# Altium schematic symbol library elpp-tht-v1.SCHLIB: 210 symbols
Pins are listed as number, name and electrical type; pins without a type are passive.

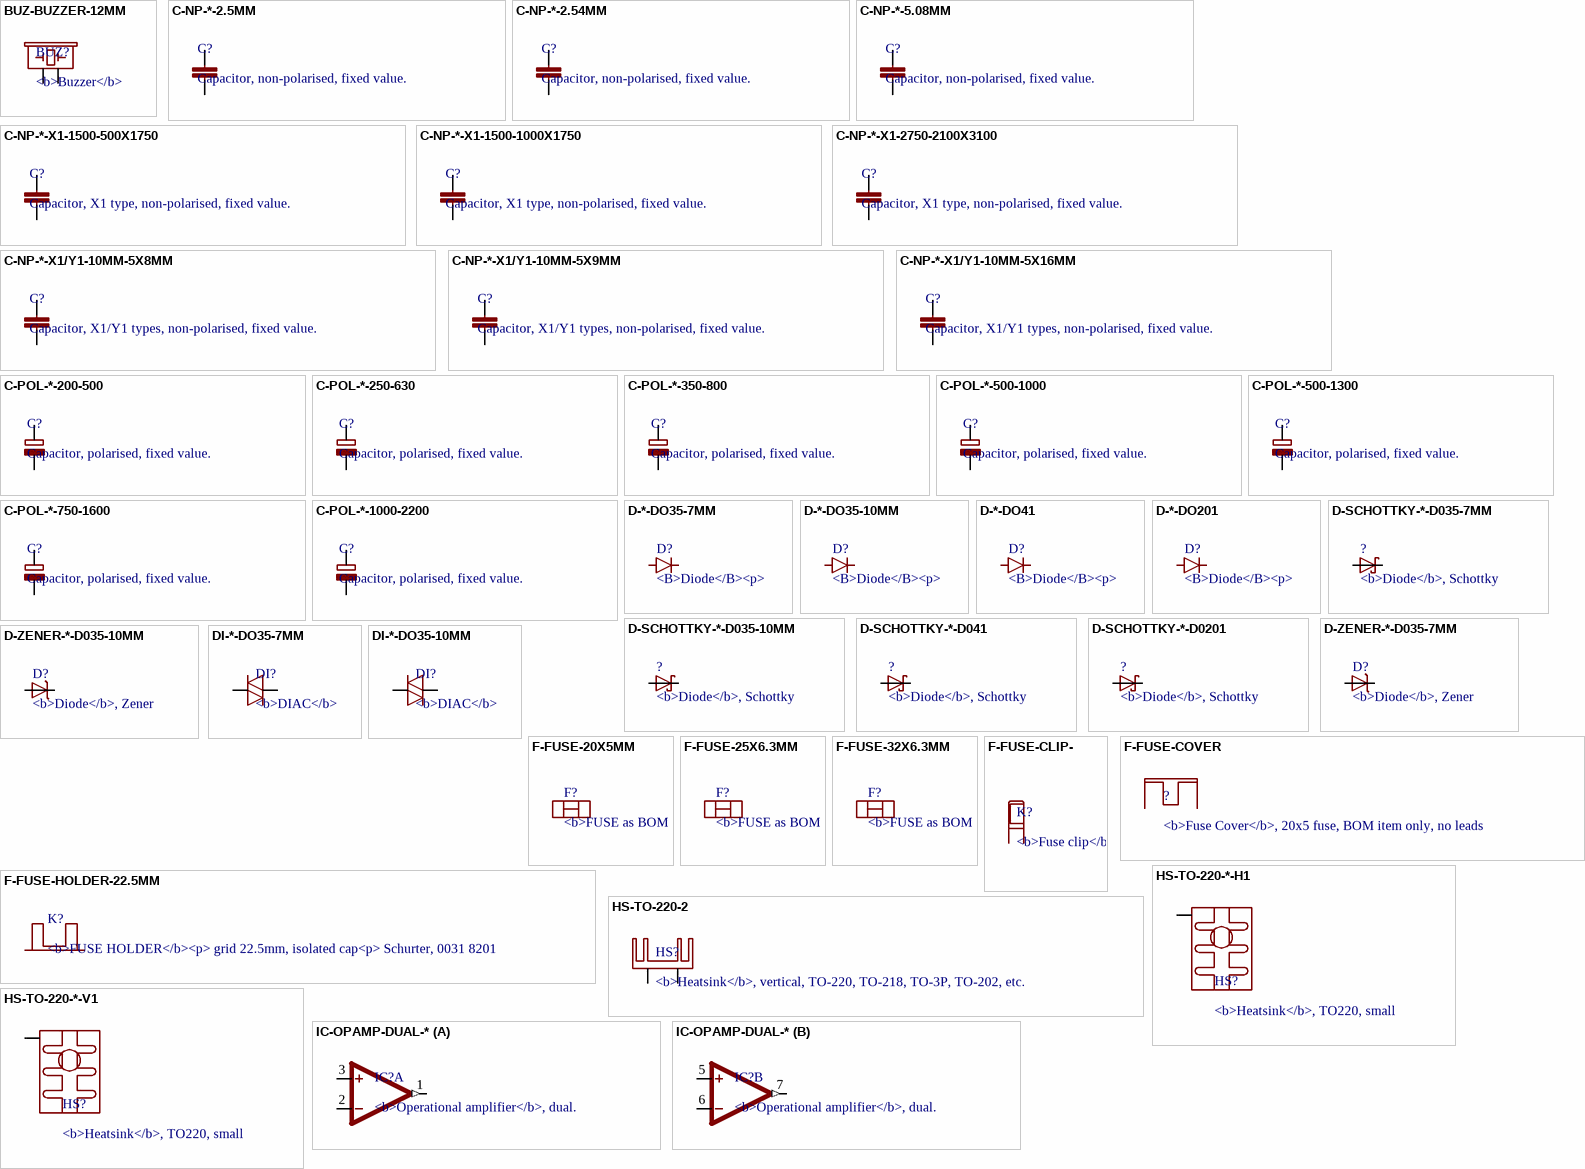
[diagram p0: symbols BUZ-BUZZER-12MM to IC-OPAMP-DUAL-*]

## BUZ-BUZZER-12MM
designator BUZ?, comment <b>Buzzer</b>
RS: 6173081
footprint ELPP-BUZZER-12MM
pins: + 1, - 2

## C-NP-*-2.5MM
designator C?, comment Capacitor, non-polarised, fixed value.
RS: 5373549; RS: 5373634; RS: 6994982; RS: 2114921
footprint ELPP-CNP-250
pins: 1, 2

## C-NP-*-2.54MM
designator C?, comment Capacitor, non-polarised, fixed value.
RS: 7368827; RS: 7368820; RS: 6530131; RS: 7368823; RS: 7368836
footprint ELPP-CNP-254
pins: 1, 2

## C-NP-*-5.08MM
designator C?, comment Capacitor, non-polarised, fixed value.
RS: 5373707; RS: 7215265; RS: 5373915; RS: 6530147
footprint ELPP-CNP-508
pins: 1, 2

## C-NP-*-X1-1500-500X1750
designator C?, comment Capacitor, X1 type, non-polarised, fixed value.
RS: 6842153
footprint ELPP-CNP-1500-500X1750
pins: 1, 2

## C-NP-*-X1-1500-1000X1750
designator C?, comment Capacitor, X1 type, non-polarised, fixed value.
RS: 6842169
footprint ELPP-CNP-1500-1000X1750
pins: 1, 2

## C-NP-*-X1-2750-2100X3100
designator C?, comment Capacitor, X1 type, non-polarised, fixed value.
RS: 6842175
footprint ELPP-CNP-2750-2100X3100
pins: 1, 2

## C-NP-*-X1/Y1-10MM-5X8MM
designator C?, comment Capacitor, X1/Y1 types, non-polarised, fixed value.
RS: 7368934
footprint ELPP-CNP-1000-500X800
pins: 1, 2

## C-NP-*-X1/Y1-10MM-5X9MM
designator C?, comment Capacitor, X1/Y1 types, non-polarised, fixed value.
RS: 7368946
footprint ELPP-CNP-1000-500X900
pins: 1, 2

## C-NP-*-X1/Y1-10MM-5X16MM
designator C?, comment Capacitor, X1/Y1 types, non-polarised, fixed value.
RS: 7368952
footprint ELPP-CNP-1000-500X1600
pins: 1, 2

## C-POL-*-200-500
designator C?, comment Capacitor, polarised, fixed value.
RS: 2286830; RS: 2286874; RS: 2286846; RS: 2286852; RS: 2286880; RS: 2286868
footprint ELPP-CP-200-500
pins: +, -

## C-POL-*-250-630
designator C?, comment Capacitor, polarised, fixed value.
RS: 2286896
footprint ELPP-CP-250-630
pins: +, -

## C-POL-*-350-800
designator C?, comment Capacitor, polarised, fixed value.
RS: 2286903
footprint ELPP-CP-350-800
pins: +, -

## C-POL-*-500-1000
designator C?, comment Capacitor, polarised, fixed value.
RS: 2286919
footprint ELPP-CP-500-1000
pins: +, -

## C-POL-*-500-1300
designator C?, comment Capacitor, polarised, fixed value.
RS: 2286925
footprint ELPP-CP-500-1300
pins: +, -

## C-POL-*-750-1600
designator C?, comment Capacitor, polarised, fixed value.
RS: 2287013; RS: 3654335
footprint ELPP-CP-750-1600
pins: +, -

## C-POL-*-1000-2200
designator C?, comment Capacitor, polarised, fixed value.
RS: 7111526
footprint ELPP-CP-1000-2200
pins: +, -

## D-*-DO35-7MM
designator D?, comment <B>Diode</B><p>
RS: 5443480
footprint ELPP-DO-35-7MM
pins: A, C

## D-*-DO35-10MM
designator D?, comment <B>Diode</B><p>
RS: 5443480
footprint ELPP-DO-35-10MM
pins: A, C

## D-*-DO41
designator D?, comment <B>Diode</B><p>
RS: 6715468
footprint ELPP-DO-41
pins: A, C

## D-*-DO201
designator D?, comment <B>Diode</B><p>
RS: 7003879
footprint ELPP-DO-201AD
pins: A, C

## D-SCHOTTKY-*-D035-7MM
designator ?, comment <b>Diode</b>, Schottky
RS: 7003857
footprint ELPP-DO-35-7MM
pins: A, C

## D-SCHOTTKY-*-D035-10MM
designator ?, comment <b>Diode</b>, Schottky
RS: 7003857
footprint ELPP-DO-35-10MM
pins: A, C

## D-SCHOTTKY-*-D041
designator ?, comment <b>Diode</b>, Schottky
RS: 7146807
footprint ELPP-DO-41
pins: A, C

## D-SCHOTTKY-*-D0201
designator ?, comment <b>Diode</b>, Schottky
RS: 7010215
footprint ELPP-DO-201AD
pins: A, C

## D-ZENER-*-D035-7MM
designator D?, comment <b>Diode</b>, Zener
RS: 6997783; RS: 6997792; RS: 7087883; RS: 6997799; RS: 6997802
footprint ELPP-DO-35-7MM
pins: A, C

## D-ZENER-*-D035-10MM
designator D?, comment <b>Diode</b>, Zener
RS: 6997783; RS: 6997792; RS: 7087883; RS: 6997799; RS: 6997802
footprint ELPP-DO-35-10MM
pins: A, C

## DI-*-DO35-7MM
designator DI?, comment <b>DIAC</b>
RS: 108132
footprint ELPP-DO-35-7MM
pins: A 1, C 2

## DI-*-DO35-10MM
designator DI?, comment <b>DIAC</b>
RS: 108132
footprint ELPP-DO-35-10MM
pins: A 1, C 2

## F-FUSE-20X5MM
designator F?, comment <b>FUSE as BOM item</b><p>No leads, add <u>one</u> fuse holder or <u>two</u> fuse clips for fuse leads</p>
footprint ELPP-FUSE-2000X500

## F-FUSE-25X6.3MM
designator F?, comment <b>FUSE as BOM item</b><p>No leads, add <u>one</u> fuse holder or <u>two</u> fuse clips for fuse leads</p>
footprint ELPP-FUSE-2500X630

## F-FUSE-32X6.3MM
designator F?, comment <b>FUSE as BOM item</b><p>No leads, add <u>one</u> fuse holder or <u>two</u> fuse clips for fuse leads</p>
footprint ELPP-FUSE-3200X630

## F-FUSE-CLIP-
designator K?, comment <b>Fuse clip</b> for 6.3mm diameter fuses.<br>You need two of these for one fuse.
RS: 7032798
footprint ELPP-FUSE-CLIP
pins: 1A 1, 1B 2

## F-FUSE-COVER
designator ?, comment <b>Fuse Cover</b>, 20x5 fuse, BOM item only, no leads
RS: 1769069

## F-FUSE-HOLDER-22.5MM
designator K?, comment <b>FUSE HOLDER</b><p> grid 22.5mm, isolated cap<p> Schurter, 0031 8201
RS: 1769047
footprint ELPP-FUSE-HOLDER-2000X500
pins: 1, 2

## HS-TO-220-2
designator HS?, comment <b>Heatsink</b>, vertical, TO-220, TO-218, TO-3P, TO-202, etc.
RS: 403190
footprint ELPP-HS-TO-220-V2
pins: 1 (oe), 2 (oe)

## HS-TO-220-*-H1
designator HS?, comment <b>Heatsink</b>, TO220, small
RS: 268082
footprint ELPP-HS-TO-220-H1
pins: 1

## HS-TO-220-*-V1
designator HS?, comment <b>Heatsink</b>, TO220, small
RS: 7124248
footprint ELPP-HS-TO-220-V1
pins: 1

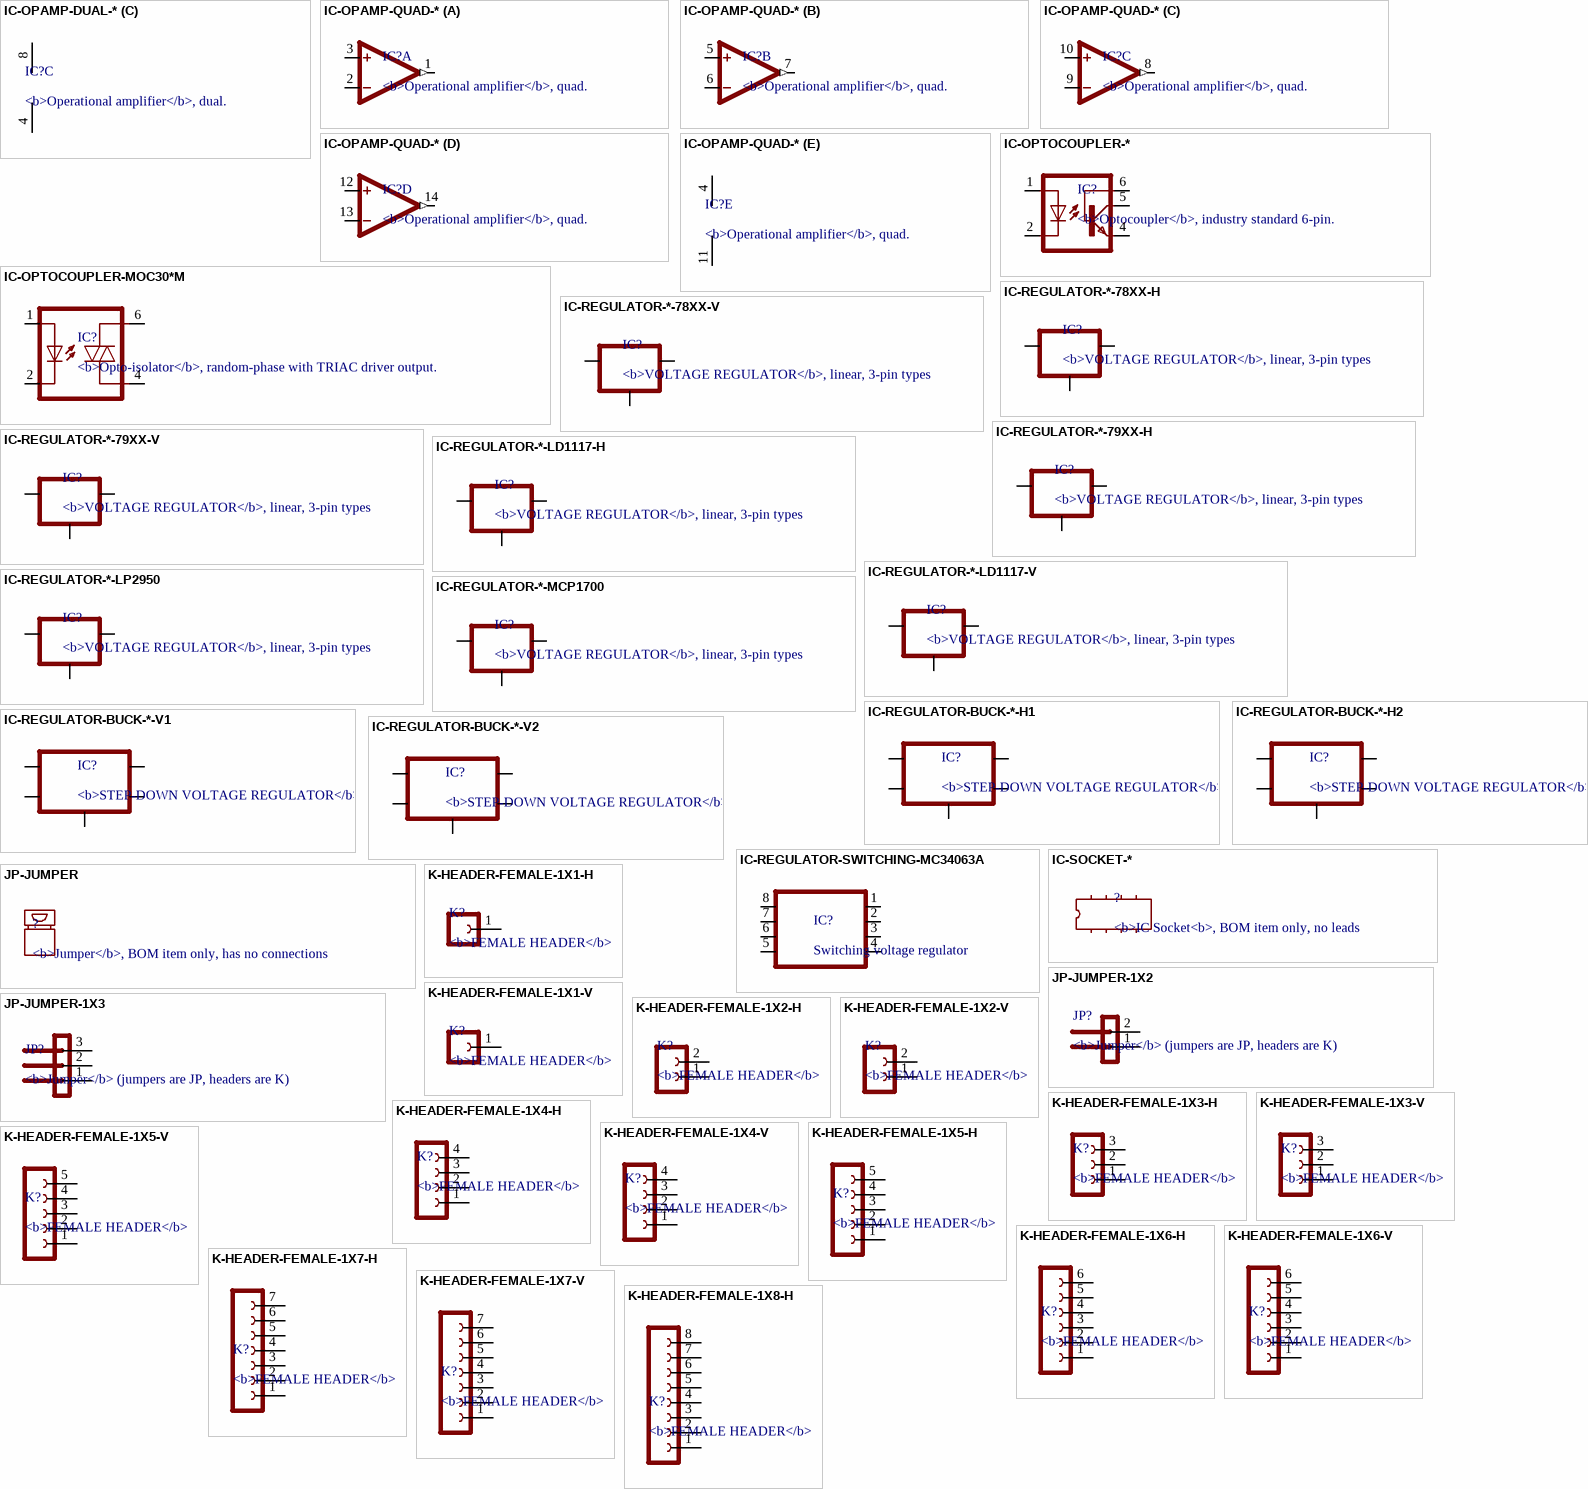
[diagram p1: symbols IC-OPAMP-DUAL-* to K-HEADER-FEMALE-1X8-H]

## IC-OPAMP-DUAL-*
designator IC?, comment <b>Operational amplifier</b>, dual.
RS: 7613546; RS: 4363046; RS: 304239
footprint ELPP-DIP-8
part A pins: 1 OUT (out), 2 -IN, 3 +IN
part B pins: 5 +IN, 6 -IN, 7 OUT (out)
part C pins: 4 V-, 8 V+

## IC-OPAMP-QUAD-*
designator IC?, comment <b>Operational amplifier</b>, quad.
RS: 6610530; RS: 403181; RS: 302621
footprint ELPP-DIP-14
part A pins: 1 OUT (out), 2 -IN, 3 +IN
part B pins: 5 +IN, 6 -IN, 7 OUT (out)
part C pins: 8 OUT (out), 9 -IN, 10 +IN
part D pins: 12 +IN, 13 -IN, 14 OUT (out)
part E pins: 4 V+, 11 V-

## IC-OPTOCOUPLER-*
designator IC?, comment <b>Optocoupler</b>, industry standard 6-pin.
RS: 6998155
footprint ELPP-DIP-6
pins: 1 A, 2 C, 4 EMI, 5 COL, 6 BAS

## IC-OPTOCOUPLER-MOC30*M
designator IC?, comment <b>Opto-isolator</b>, random-phase with TRIAC driver output.
RS: 6711422
footprint ELPP-DIP-6
pins: 1 A, 2 C, 4 A1, 6 A2

## IC-REGULATOR-*-78XX-H
designator IC?, comment <b>VOLTAGE REGULATOR</b>, linear, 3-pin types
RS: 5164834; RS: 5164840; RS: 5164799; RS: 5164812
footprint ELPP-TO-220-H
pins: 1 VI, 2 COM, 3 VO

## IC-REGULATOR-*-78XX-V
designator IC?, comment <b>VOLTAGE REGULATOR</b>, linear, 3-pin types
RS: 5164834; RS: 5164840; RS: 5164799; RS: 5164812
footprint ELPP-TO-220-V
pins: 1 VI, 2 COM, 3 VO

## IC-REGULATOR-*-79XX-H
designator IC?, comment <b>VOLTAGE REGULATOR</b>, linear, 3-pin types
RS: 5166228
footprint ELPP-TO-220-H
pins: 1 VI, 2 COM, 3 VO

## IC-REGULATOR-*-79XX-V
designator IC?, comment <b>VOLTAGE REGULATOR</b>, linear, 3-pin types
RS: 5166228
footprint ELPP-TO-220-V
pins: 1 VI, 2 COM, 3 VO

## IC-REGULATOR-*-LD1117-H
designator IC?, comment <b>VOLTAGE REGULATOR</b>, linear, 3-pin types
RS: 6869767
footprint ELPP-TO-220-H
pins: 1 COM, 2 VO, 3 VI

## IC-REGULATOR-*-LD1117-V
designator IC?, comment <b>VOLTAGE REGULATOR</b>, linear, 3-pin types
RS: 6869767
footprint ELPP-TO-220-V
pins: 1 COM, 2 VO, 3 VI

## IC-REGULATOR-*-LP2950
designator IC?, comment <b>VOLTAGE REGULATOR</b>, linear, 3-pin types
RS: 5344901
footprint ELPP-TO-92
pins: 1 VO, 2 COM, 3 VI

## IC-REGULATOR-*-MCP1700
designator IC?, comment <b>VOLTAGE REGULATOR</b>, linear, 3-pin types
RS: 403888
footprint ELPP-TO-92
pins: 1 COM, 2 VI, 3 VO

## IC-REGULATOR-BUCK-*-H1
designator IC?, comment <b>STEP-DOWN VOLTAGE REGULATOR</b>
RS: 5338108
footprint ELPP-TO-220-5-H
pins: 1 VI, 2 VO, 3 COM, 4 FB, 5 EN

## IC-REGULATOR-BUCK-*-H2
designator IC?, comment <b>STEP-DOWN VOLTAGE REGULATOR</b>
RS: 5338108
footprint ELPP-TO-220-5-H-STAGGERED
pins: 1 VI, 2 VO, 3 COM, 4 FB, 5 EN

## IC-REGULATOR-BUCK-*-V1
designator IC?, comment <b>STEP-DOWN VOLTAGE REGULATOR</b>
RS: 5338108
footprint ELPP-TO-220-5-V
pins: 1 VI, 2 VO, 3 COM, 4 FB, 5 EN

## IC-REGULATOR-BUCK-*-V2
designator IC?, comment <b>STEP-DOWN VOLTAGE REGULATOR</b>
RS: 5338108
footprint ELPP-TO-220-5-V-STAGGERED
pins: 1 VI, 2 VO, 3 COM, 4 FB, 5 EN

## IC-REGULATOR-SWITCHING-MC34063A
designator IC?, comment Switching voltage regulator
RS: 6618430
footprint ELPP-DIP-8
pins: 1, 2, 3, 4, 5, 6, 7, 8

## IC-SOCKET-*
designator ?, comment <b>IC Socket<b>, BOM item only, no leads
RS: 7020676; RS: 7020688; RS: 7022723; RS: 7022726; RS: 7022745; RS: 7022798; RS: 7020657; RS: 7020654

## JP-JUMPER
designator ?, comment <b>Jumper</b>, BOM item only, has no connections
RS: 2509565244

## JP-JUMPER-1X2
designator JP?, comment <b>Jumper</b> (jumpers are JP, headers are K)
RS: 6812058
footprint ELPP-SIL-M-2-WAY
pins: 1, 2

## JP-JUMPER-1X3
designator JP?, comment <b>Jumper</b> (jumpers are JP, headers are K)
RS: 6812058
footprint ELPP-SIL-M-3-WAY
pins: 1, 2, 3

## K-HEADER-FEMALE-1X1-H
designator K?, comment <b>FEMALE HEADER</b>
RS: unknown
footprint ELPP-SIL-F-1-WAY-90DEG
pins: 1

## K-HEADER-FEMALE-1X1-V
designator K?, comment <b>FEMALE HEADER</b>
RS: unknown
footprint ELPP-SIL-F-1-WAY
pins: 1

## K-HEADER-FEMALE-1X2-H
designator K?, comment <b>FEMALE HEADER</b>
RS: unknown
footprint ELPP-SIL-F-2-WAY-90DEG
pins: 1, 2

## K-HEADER-FEMALE-1X2-V
designator K?, comment <b>FEMALE HEADER</b>
RS: unknown
footprint ELPP-SIL-F-2-WAY
pins: 1, 2

## K-HEADER-FEMALE-1X3-H
designator K?, comment <b>FEMALE HEADER</b>
RS: unknown
footprint ELPP-SIL-F-3-WAY-90DEG
pins: 1, 2, 3

## K-HEADER-FEMALE-1X3-V
designator K?, comment <b>FEMALE HEADER</b>
RS: unknown
footprint ELPP-SIL-F-3-WAY
pins: 1, 2, 3

## K-HEADER-FEMALE-1X4-H
designator K?, comment <b>FEMALE HEADER</b>
RS: unknown
footprint ELPP-SIL-F-4-WAY-90DEG
pins: 1, 2, 3, 4

## K-HEADER-FEMALE-1X4-V
designator K?, comment <b>FEMALE HEADER</b>
RS: unknown
footprint ELPP-SIL-F-4-WAY
pins: 1, 2, 3, 4

## K-HEADER-FEMALE-1X5-H
designator K?, comment <b>FEMALE HEADER</b>
RS: unknown
footprint ELPP-SIL-F-5-WAY-90DEG
pins: 1, 2, 3, 4, 5

## K-HEADER-FEMALE-1X5-V
designator K?, comment <b>FEMALE HEADER</b>
RS: unknown
footprint ELPP-SIL-F-5-WAY
pins: 1, 2, 3, 4, 5

## K-HEADER-FEMALE-1X6-H
designator K?, comment <b>FEMALE HEADER</b>
RS: unknown
footprint ELPP-SIL-F-6-WAY-90DEG
pins: 1, 2, 3, 4, 5, 6

## K-HEADER-FEMALE-1X6-V
designator K?, comment <b>FEMALE HEADER</b>
RS: unknown
footprint ELPP-SIL-F-6-WAY
pins: 1, 2, 3, 4, 5, 6

## K-HEADER-FEMALE-1X7-H
designator K?, comment <b>FEMALE HEADER</b>
RS: unknown
footprint ELPP-SIL-F-7-WAY-90DEG
pins: 1, 2, 3, 4, 5, 6, 7

## K-HEADER-FEMALE-1X7-V
designator K?, comment <b>FEMALE HEADER</b>
RS: unknown
footprint ELPP-SIL-F-7-WAY
pins: 1, 2, 3, 4, 5, 6, 7

## K-HEADER-FEMALE-1X8-H
designator K?, comment <b>FEMALE HEADER</b>
RS: unknown
footprint ELPP-SIL-F-8-WAY-90DEG
pins: 1, 2, 3, 4, 5, 6, 7, 8

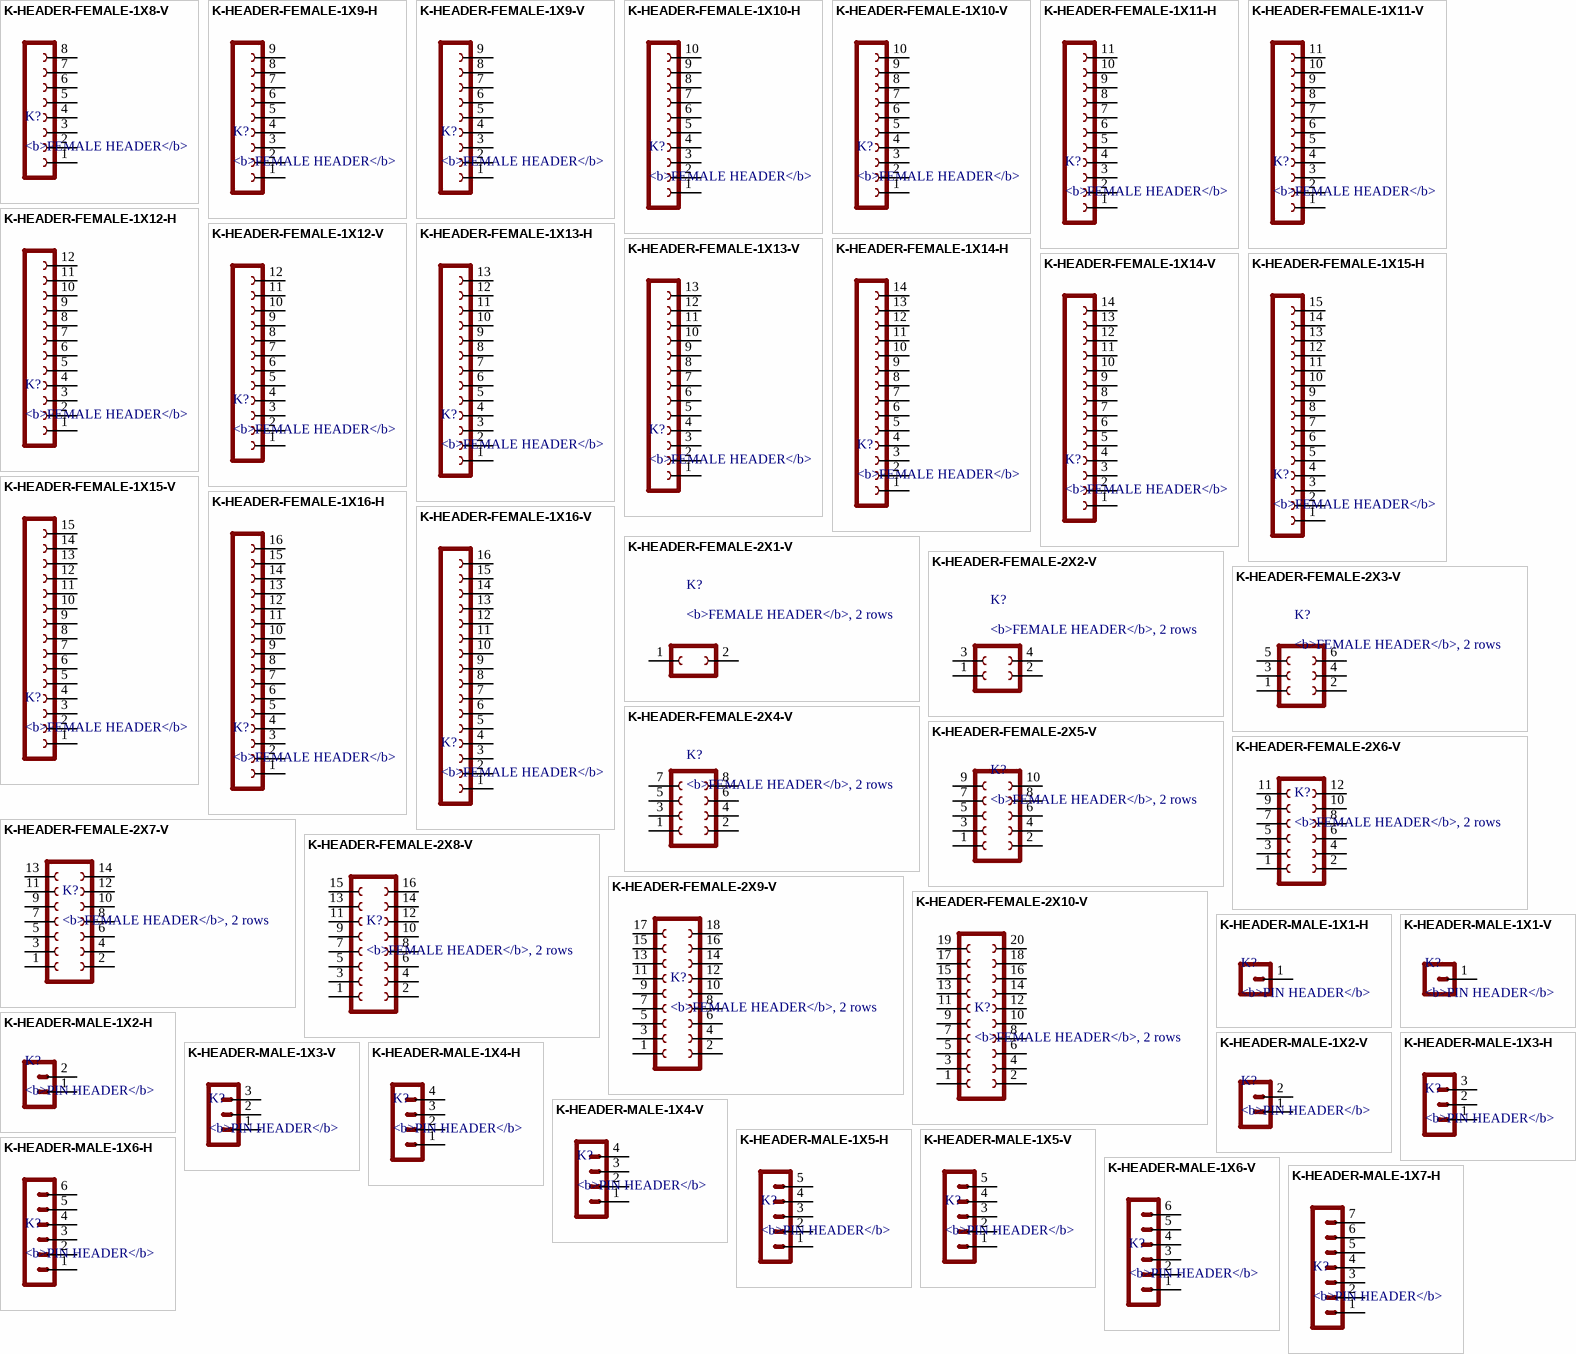
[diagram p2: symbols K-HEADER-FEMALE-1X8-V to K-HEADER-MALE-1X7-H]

## K-HEADER-FEMALE-1X8-V
designator K?, comment <b>FEMALE HEADER</b>
RS: unknown
footprint ELPP-SIL-F-8-WAY
pins: 1, 2, 3, 4, 5, 6, 7, 8

## K-HEADER-FEMALE-1X9-H
designator K?, comment <b>FEMALE HEADER</b>
RS: unknown
footprint ELPP-SIL-F-9-WAY-90DEG
pins: 1, 2, 3, 4, 5, 6, 7, 8, 9

## K-HEADER-FEMALE-1X9-V
designator K?, comment <b>FEMALE HEADER</b>
RS: unknown
footprint ELPP-SIL-F-9-WAY
pins: 1, 2, 3, 4, 5, 6, 7, 8, 9

## K-HEADER-FEMALE-1X10-H
designator K?, comment <b>FEMALE HEADER</b>
RS: unknown
footprint ELPP-SIL-F-10-WAY-90DEG
pins: 1, 2, 3, 4, 5, 6, 7, 8, 9, 10

## K-HEADER-FEMALE-1X10-V
designator K?, comment <b>FEMALE HEADER</b>
RS: unknown
footprint ELPP-SIL-F-10-WAY
pins: 1, 2, 3, 4, 5, 6, 7, 8, 9, 10

## K-HEADER-FEMALE-1X11-H
designator K?, comment <b>FEMALE HEADER</b>
RS: unknown
footprint ELPP-SIL-F-11-WAY-90DEG
pins: 1, 2, 3, 4, 5, 6, 7, 8, 9, 10, 11

## K-HEADER-FEMALE-1X11-V
designator K?, comment <b>FEMALE HEADER</b>
RS: unknown
footprint ELPP-SIL-F-11-WAY
pins: 1, 2, 3, 4, 5, 6, 7, 8, 9, 10, 11

## K-HEADER-FEMALE-1X12-H
designator K?, comment <b>FEMALE HEADER</b>
RS: unknown
footprint ELPP-SIL-F-12-WAY-90DEG
pins: 1, 2, 3, 4, 5, 6, 7, 8, 9, 10, 11, 12

## K-HEADER-FEMALE-1X12-V
designator K?, comment <b>FEMALE HEADER</b>
RS: unknown
footprint ELPP-SIL-F-12-WAY
pins: 1, 2, 3, 4, 5, 6, 7, 8, 9, 10, 11, 12

## K-HEADER-FEMALE-1X13-H
designator K?, comment <b>FEMALE HEADER</b>
RS: unknown
footprint ELPP-SIL-F-13-WAY-90DEG
pins: 1, 2, 3, 4, 5, 6, 7, 8, 9, 10, 11, 12, 13

## K-HEADER-FEMALE-1X13-V
designator K?, comment <b>FEMALE HEADER</b>
RS: unknown
footprint ELPP-SIL-F-13-WAY
pins: 1, 2, 3, 4, 5, 6, 7, 8, 9, 10, 11, 12, 13

## K-HEADER-FEMALE-1X14-H
designator K?, comment <b>FEMALE HEADER</b>
RS: unknown
footprint ELPP-SIL-F-14-WAY-90DEG
pins: 1, 2, 3, 4, 5, 6, 7, 8, 9, 10, 11, 12, 13, 14

## K-HEADER-FEMALE-1X14-V
designator K?, comment <b>FEMALE HEADER</b>
RS: unknown
footprint ELPP-SIL-F-14-WAY
pins: 1, 2, 3, 4, 5, 6, 7, 8, 9, 10, 11, 12, 13, 14

## K-HEADER-FEMALE-1X15-H
designator K?, comment <b>FEMALE HEADER</b>
RS: unknown
footprint ELPP-SIL-F-15-WAY-90DEG
pins: 1, 2, 3, 4, 5, 6, 7, 8, 9, 10, 11, 12, 13, 14, 15

## K-HEADER-FEMALE-1X15-V
designator K?, comment <b>FEMALE HEADER</b>
RS: unknown
footprint ELPP-SIL-F-15-WAY
pins: 1, 2, 3, 4, 5, 6, 7, 8, 9, 10, 11, 12, 13, 14, 15

## K-HEADER-FEMALE-1X16-H
designator K?, comment <b>FEMALE HEADER</b>
RS: unknown
footprint ELPP-SIL-F-16-WAY-90DEG
pins: 1, 2, 3, 4, 5, 6, 7, 8, 9, 10, 11, 12, 13, 14, 15, 16

## K-HEADER-FEMALE-1X16-V
designator K?, comment <b>FEMALE HEADER</b>
RS: unknown
footprint ELPP-SIL-F-16-WAY
pins: 1, 2, 3, 4, 5, 6, 7, 8, 9, 10, 11, 12, 13, 14, 15, 16

## K-HEADER-FEMALE-2X1-V
designator K?, comment <b>FEMALE HEADER</b>, 2 rows
RS: unknown
footprint ELPP-DIL-F-2-WAY-V
pins: 1, 2

## K-HEADER-FEMALE-2X2-V
designator K?, comment <b>FEMALE HEADER</b>, 2 rows
RS: unknown
footprint ELPP-DIL-F-4-WAY-V
pins: 1, 2, 3, 4

## K-HEADER-FEMALE-2X3-V
designator K?, comment <b>FEMALE HEADER</b>, 2 rows
RS: unknown
footprint ELPP-DIL-F-6-WAY-V
pins: 1, 2, 3, 4, 5, 6

## K-HEADER-FEMALE-2X4-V
designator K?, comment <b>FEMALE HEADER</b>, 2 rows
RS: unknown
footprint ELPP-DIL-F-8-WAY-V
pins: 1, 2, 3, 4, 5, 6, 7, 8

## K-HEADER-FEMALE-2X5-V
designator K?, comment <b>FEMALE HEADER</b>, 2 rows
RS: unknown
footprint ELPP-DIL-F-10-WAY-V
pins: 1, 2, 3, 4, 5, 6, 7, 8, 9, 10

## K-HEADER-FEMALE-2X6-V
designator K?, comment <b>FEMALE HEADER</b>, 2 rows
RS: unknown
footprint ELPP-DIL-F-12-WAY-V
pins: 1, 2, 3, 4, 5, 6, 7, 8, 9, 10, 11, 12

## K-HEADER-FEMALE-2X7-V
designator K?, comment <b>FEMALE HEADER</b>, 2 rows
RS: unknown
footprint ELPP-DIL-F-14-WAY-V
pins: 1, 2, 3, 4, 5, 6, 7, 8, 9, 10, 11, 12, 13, 14

## K-HEADER-FEMALE-2X8-V
designator K?, comment <b>FEMALE HEADER</b>, 2 rows
RS: unknown
footprint ELPP-DIL-F-16-WAY-V
pins: 1, 2, 3, 4, 5, 6, 7, 8, 9, 10, 11, 12, 13, 14, 15, 16

## K-HEADER-FEMALE-2X9-V
designator K?, comment <b>FEMALE HEADER</b>, 2 rows
RS: unknown
footprint ELPP-DIL-F-18-WAY-V
pins: 1, 2, 3, 4, 5, 6, 7, 8, 9, 10, 11, 12, 13, 14, 15, 16, 17, 18

## K-HEADER-FEMALE-2X10-V
designator K?, comment <b>FEMALE HEADER</b>, 2 rows
RS: unknown
footprint ELPP-DIL-F-20-WAY-V
pins: 1, 2, 3, 4, 5, 6, 7, 8, 9, 10, 11, 12, 13, 14, 15, 16, 17, 18, 19, 20

## K-HEADER-MALE-1X1-H
designator K?, comment <b>PIN HEADER</b>
RS: 6812060
footprint ELPP-SIL-M-1-WAY-90DEG
pins: 1

## K-HEADER-MALE-1X1-V
designator K?, comment <b>PIN HEADER</b>
RS: 6812058
footprint ELPP-SIL-M-1-WAY
pins: 1

## K-HEADER-MALE-1X2-H
designator K?, comment <b>PIN HEADER</b>
RS: 6812060
footprint ELPP-SIL-M-2-WAY-90DEG
pins: 1, 2

## K-HEADER-MALE-1X2-V
designator K?, comment <b>PIN HEADER</b>
RS: 6812058
footprint ELPP-SIL-M-2-WAY
pins: 1, 2

## K-HEADER-MALE-1X3-H
designator K?, comment <b>PIN HEADER</b>
RS: 6812060
footprint ELPP-SIL-M-3-WAY-90DEG
pins: 1, 2, 3

## K-HEADER-MALE-1X3-V
designator K?, comment <b>PIN HEADER</b>
RS: 6812058
footprint ELPP-SIL-M-3-WAY
pins: 1, 2, 3

## K-HEADER-MALE-1X4-H
designator K?, comment <b>PIN HEADER</b>
RS: 6812060
footprint ELPP-SIL-M-4-WAY-90DEG
pins: 1, 2, 3, 4

## K-HEADER-MALE-1X4-V
designator K?, comment <b>PIN HEADER</b>
RS: 6812058
footprint ELPP-SIL-M-4-WAY
pins: 1, 2, 3, 4

## K-HEADER-MALE-1X5-H
designator K?, comment <b>PIN HEADER</b>
RS: 6812060
footprint ELPP-SIL-M-5-WAY-90DEG
pins: 1, 2, 3, 4, 5

## K-HEADER-MALE-1X5-V
designator K?, comment <b>PIN HEADER</b>
RS: 6812058
footprint ELPP-SIL-M-5-WAY
pins: 1, 2, 3, 4, 5

## K-HEADER-MALE-1X6-H
designator K?, comment <b>PIN HEADER</b>
RS: 6812060
footprint ELPP-SIL-M-6-WAY-90DEG
pins: 1, 2, 3, 4, 5, 6

## K-HEADER-MALE-1X6-V
designator K?, comment <b>PIN HEADER</b>
RS: 6812058
footprint ELPP-SIL-M-6-WAY
pins: 1, 2, 3, 4, 5, 6

## K-HEADER-MALE-1X7-H
designator K?, comment <b>PIN HEADER</b>
RS: 6812060
footprint ELPP-SIL-M-7-WAY-90DEG
pins: 1, 2, 3, 4, 5, 6, 7

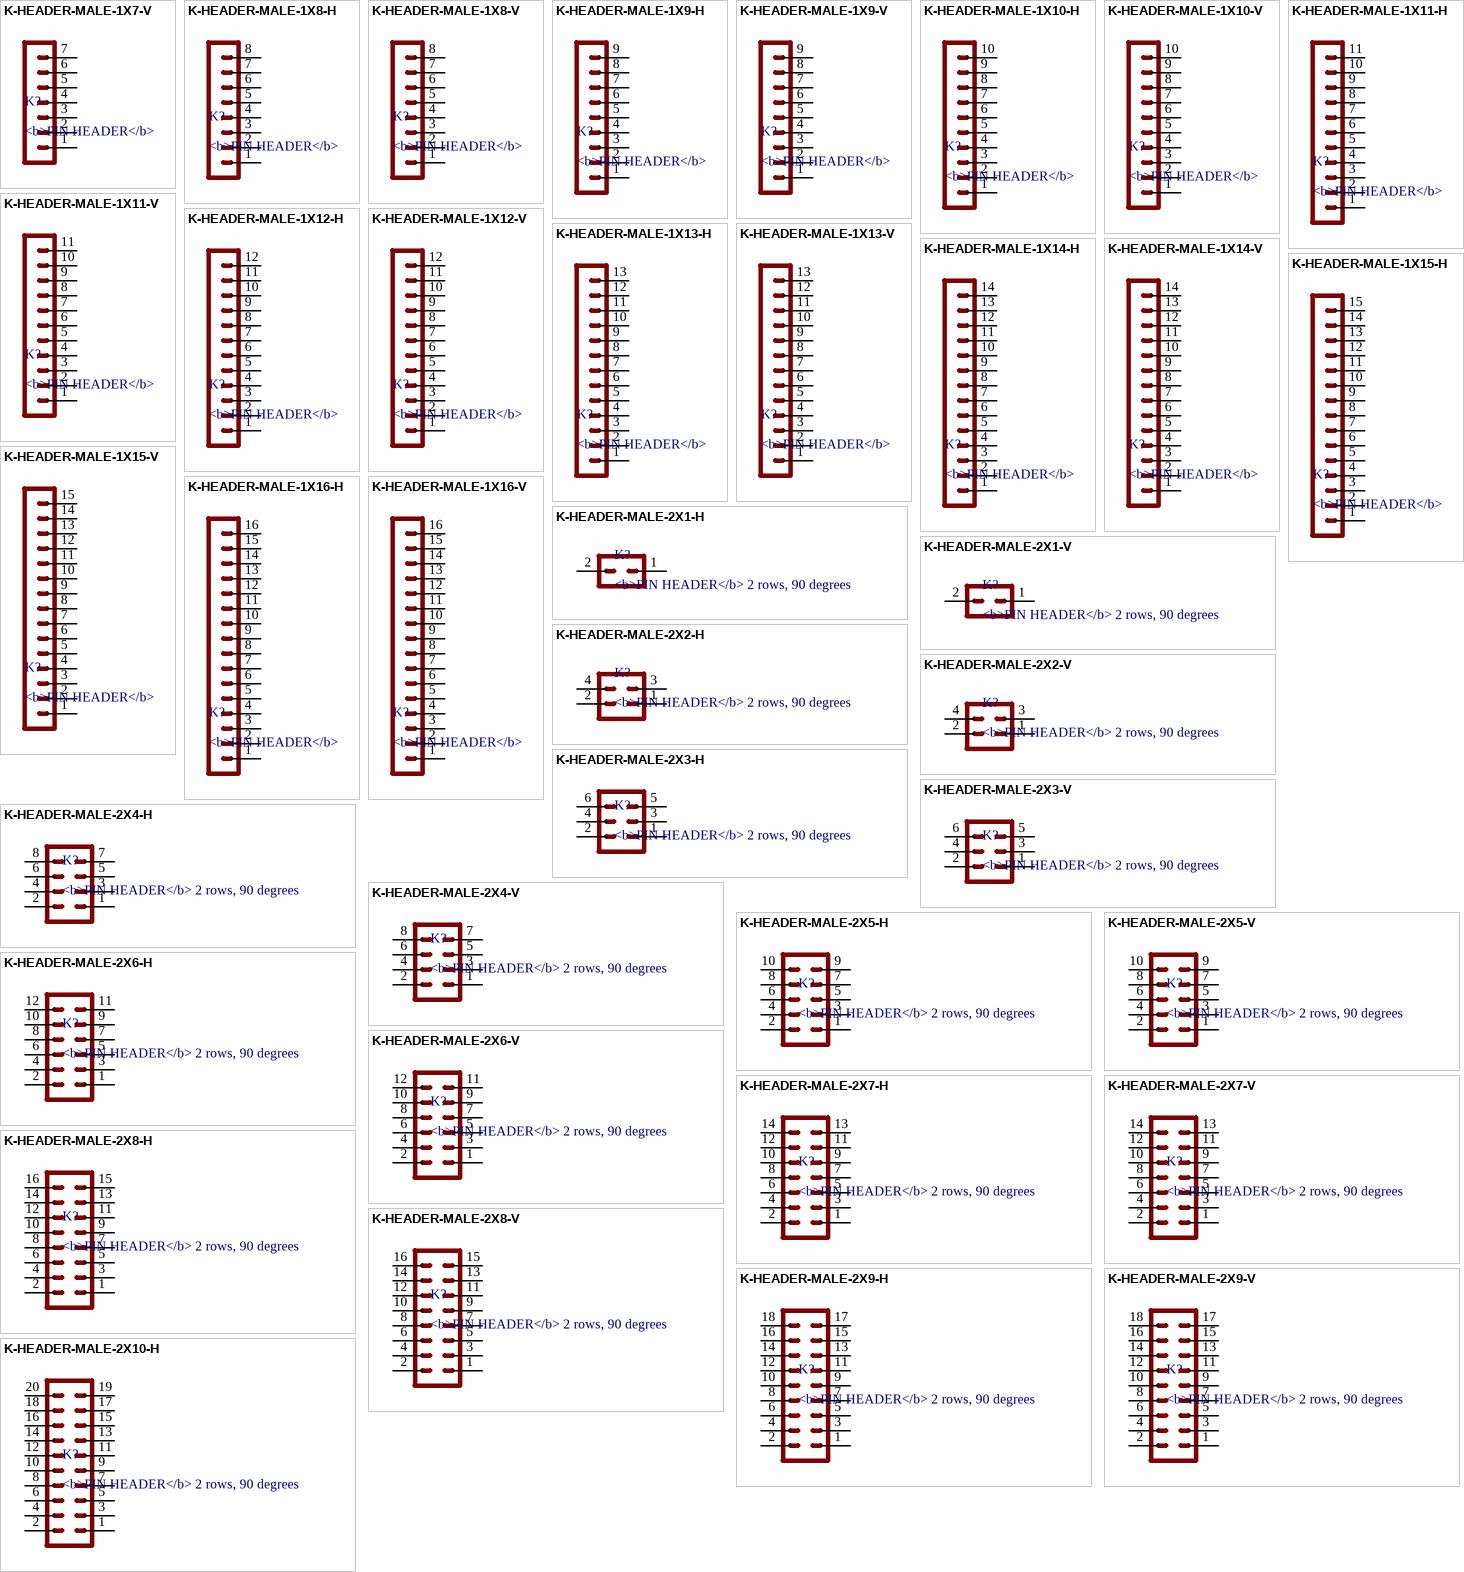
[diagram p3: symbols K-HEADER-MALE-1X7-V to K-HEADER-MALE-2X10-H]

## K-HEADER-MALE-1X7-V
designator K?, comment <b>PIN HEADER</b>
RS: 6812058
footprint ELPP-SIL-M-7-WAY
pins: 1, 2, 3, 4, 5, 6, 7

## K-HEADER-MALE-1X8-H
designator K?, comment <b>PIN HEADER</b>
RS: 6812060
footprint ELPP-SIL-M-8-WAY-90DEG
pins: 1, 2, 3, 4, 5, 6, 7, 8

## K-HEADER-MALE-1X8-V
designator K?, comment <b>PIN HEADER</b>
RS: 6812058
footprint ELPP-SIL-M-8-WAY
pins: 1, 2, 3, 4, 5, 6, 7, 8

## K-HEADER-MALE-1X9-H
designator K?, comment <b>PIN HEADER</b>
RS: 6812060
footprint ELPP-SIL-M-9-WAY-90DEG
pins: 1, 2, 3, 4, 5, 6, 7, 8, 9

## K-HEADER-MALE-1X9-V
designator K?, comment <b>PIN HEADER</b>
RS: 6812058
footprint ELPP-SIL-M-9-WAY
pins: 1, 2, 3, 4, 5, 6, 7, 8, 9

## K-HEADER-MALE-1X10-H
designator K?, comment <b>PIN HEADER</b>
RS: 6812060
footprint ELPP-SIL-M-10-WAY-90DEG
pins: 1, 2, 3, 4, 5, 6, 7, 8, 9, 10

## K-HEADER-MALE-1X10-V
designator K?, comment <b>PIN HEADER</b>
RS: 6812058
footprint ELPP-SIL-M-10-WAY
pins: 1, 2, 3, 4, 5, 6, 7, 8, 9, 10

## K-HEADER-MALE-1X11-H
designator K?, comment <b>PIN HEADER</b>
RS: 6812060
footprint ELPP-SIL-M-11-WAY-90DEG
pins: 1, 2, 3, 4, 5, 6, 7, 8, 9, 10, 11

## K-HEADER-MALE-1X11-V
designator K?, comment <b>PIN HEADER</b>
RS: 6812058
footprint ELPP-SIL-M-11-WAY
pins: 1, 2, 3, 4, 5, 6, 7, 8, 9, 10, 11

## K-HEADER-MALE-1X12-H
designator K?, comment <b>PIN HEADER</b>
RS: 6812060
footprint ELPP-SIL-M-12-WAY-90DEG
pins: 1, 2, 3, 4, 5, 6, 7, 8, 9, 10, 11, 12

## K-HEADER-MALE-1X12-V
designator K?, comment <b>PIN HEADER</b>
RS: 6812058
footprint ELPP-SIL-M-12-WAY
pins: 1, 2, 3, 4, 5, 6, 7, 8, 9, 10, 11, 12

## K-HEADER-MALE-1X13-H
designator K?, comment <b>PIN HEADER</b>
RS: 6812060
footprint ELPP-SIL-M-13-WAY-90DEG
pins: 1, 2, 3, 4, 5, 6, 7, 8, 9, 10, 11, 12, 13

## K-HEADER-MALE-1X13-V
designator K?, comment <b>PIN HEADER</b>
RS: 6812058
footprint ELPP-SIL-M-13-WAY
pins: 1, 2, 3, 4, 5, 6, 7, 8, 9, 10, 11, 12, 13

## K-HEADER-MALE-1X14-H
designator K?, comment <b>PIN HEADER</b>
RS: 6812060
footprint ELPP-SIL-M-14-WAY-90DEG
pins: 1, 2, 3, 4, 5, 6, 7, 8, 9, 10, 11, 12, 13, 14

## K-HEADER-MALE-1X14-V
designator K?, comment <b>PIN HEADER</b>
RS: 6812058
footprint ELPP-SIL-M-14-WAY
pins: 1, 2, 3, 4, 5, 6, 7, 8, 9, 10, 11, 12, 13, 14

## K-HEADER-MALE-1X15-H
designator K?, comment <b>PIN HEADER</b>
RS: 6812060
footprint ELPP-SIL-M-15-WAY-90DEG
pins: 1, 2, 3, 4, 5, 6, 7, 8, 9, 10, 11, 12, 13, 14, 15

## K-HEADER-MALE-1X15-V
designator K?, comment <b>PIN HEADER</b>
RS: 6812058
footprint ELPP-SIL-M-15-WAY
pins: 1, 2, 3, 4, 5, 6, 7, 8, 9, 10, 11, 12, 13, 14, 15

## K-HEADER-MALE-1X16-H
designator K?, comment <b>PIN HEADER</b>
RS: 6812060
footprint ELPP-SIL-M-16-WAY-90DEG
pins: 1, 2, 3, 4, 5, 6, 7, 8, 9, 10, 11, 12, 13, 14, 15, 16

## K-HEADER-MALE-1X16-V
designator K?, comment <b>PIN HEADER</b>
RS: 6812058
footprint ELPP-SIL-M-16-WAY
pins: 1, 2, 3, 4, 5, 6, 7, 8, 9, 10, 11, 12, 13, 14, 15, 16

## K-HEADER-MALE-2X1-H
designator K?, comment <b>PIN HEADER</b> 2 rows, 90 degrees
RS: 6812666
footprint ELPP-DIL-M-2-WAY-H
pins: 1, 2

## K-HEADER-MALE-2X1-V
designator K?, comment <b>PIN HEADER</b> 2 rows, 90 degrees
RS: 6812067
footprint ELPP-DIL-M-2-WAY-V
pins: 1, 2

## K-HEADER-MALE-2X2-H
designator K?, comment <b>PIN HEADER</b> 2 rows, 90 degrees
RS: 6812666
footprint ELPP-DIL-M-4-WAY-H
pins: 1, 2, 3, 4

## K-HEADER-MALE-2X2-V
designator K?, comment <b>PIN HEADER</b> 2 rows, 90 degrees
RS: 6812067
footprint ELPP-DIL-M-4-WAY-V
pins: 1, 2, 3, 4

## K-HEADER-MALE-2X3-H
designator K?, comment <b>PIN HEADER</b> 2 rows, 90 degrees
RS: 6812666
footprint ELPP-DIL-M-6-WAY-H
pins: 1, 2, 3, 4, 5, 6

## K-HEADER-MALE-2X3-V
designator K?, comment <b>PIN HEADER</b> 2 rows, 90 degrees
RS: 6812067
footprint ELPP-DIL-M-6-WAY-V
pins: 1, 2, 3, 4, 5, 6

## K-HEADER-MALE-2X4-H
designator K?, comment <b>PIN HEADER</b> 2 rows, 90 degrees
RS: 6812666
footprint ELPP-DIL-M-8-WAY-H
pins: 1, 2, 3, 4, 5, 6, 7, 8

## K-HEADER-MALE-2X4-V
designator K?, comment <b>PIN HEADER</b> 2 rows, 90 degrees
RS: 6812067
footprint ELPP-DIL-M-8-WAY-V
pins: 1, 2, 3, 4, 5, 6, 7, 8

## K-HEADER-MALE-2X5-H
designator K?, comment <b>PIN HEADER</b> 2 rows, 90 degrees
RS: 6812666
footprint ELPP-DIL-M-10-WAY-H
pins: 1, 2, 3, 4, 5, 6, 7, 8, 9, 10

## K-HEADER-MALE-2X5-V
designator K?, comment <b>PIN HEADER</b> 2 rows, 90 degrees
RS: 6812067
footprint ELPP-DIL-M-10-WAY-V
pins: 1, 2, 3, 4, 5, 6, 7, 8, 9, 10

## K-HEADER-MALE-2X6-H
designator K?, comment <b>PIN HEADER</b> 2 rows, 90 degrees
RS: 6812666
footprint ELPP-DIL-M-12-WAY-H
pins: 1, 2, 3, 4, 5, 6, 7, 8, 9, 10, 11, 12

## K-HEADER-MALE-2X6-V
designator K?, comment <b>PIN HEADER</b> 2 rows, 90 degrees
RS: 6812067
footprint ELPP-DIL-M-12-WAY-V
pins: 1, 2, 3, 4, 5, 6, 7, 8, 9, 10, 11, 12

## K-HEADER-MALE-2X7-H
designator K?, comment <b>PIN HEADER</b> 2 rows, 90 degrees
RS: 6812666
footprint ELPP-DIL-M-14-WAY-H
pins: 1, 2, 3, 4, 5, 6, 7, 8, 9, 10, 11, 12, 13, 14

## K-HEADER-MALE-2X7-V
designator K?, comment <b>PIN HEADER</b> 2 rows, 90 degrees
RS: 6812067
footprint ELPP-DIL-M-14-WAY-V
pins: 1, 2, 3, 4, 5, 6, 7, 8, 9, 10, 11, 12, 13, 14

## K-HEADER-MALE-2X8-H
designator K?, comment <b>PIN HEADER</b> 2 rows, 90 degrees
RS: 6812666
footprint ELPP-DIL-M-16-WAY-H
pins: 1, 2, 3, 4, 5, 6, 7, 8, 9, 10, 11, 12, 13, 14, 15, 16

## K-HEADER-MALE-2X8-V
designator K?, comment <b>PIN HEADER</b> 2 rows, 90 degrees
RS: 6812067
footprint ELPP-DIL-M-16-WAY-V
pins: 1, 2, 3, 4, 5, 6, 7, 8, 9, 10, 11, 12, 13, 14, 15, 16

## K-HEADER-MALE-2X9-H
designator K?, comment <b>PIN HEADER</b> 2 rows, 90 degrees
RS: 6812666
footprint ELPP-DIL-M-18-WAY-H
pins: 1, 2, 3, 4, 5, 6, 7, 8, 9, 10, 11, 12, 13, 14, 15, 16, 17, 18

## K-HEADER-MALE-2X9-V
designator K?, comment <b>PIN HEADER</b> 2 rows, 90 degrees
RS: 6812067
footprint ELPP-DIL-M-18-WAY-V
pins: 1, 2, 3, 4, 5, 6, 7, 8, 9, 10, 11, 12, 13, 14, 15, 16, 17, 18

## K-HEADER-MALE-2X10-H
designator K?, comment <b>PIN HEADER</b> 2 rows, 90 degrees
RS: 6812666
footprint ELPP-DIL-M-20-WAY-H
pins: 1, 2, 3, 4, 5, 6, 7, 8, 9, 10, 11, 12, 13, 14, 15, 16, 17, 18, 19, 20

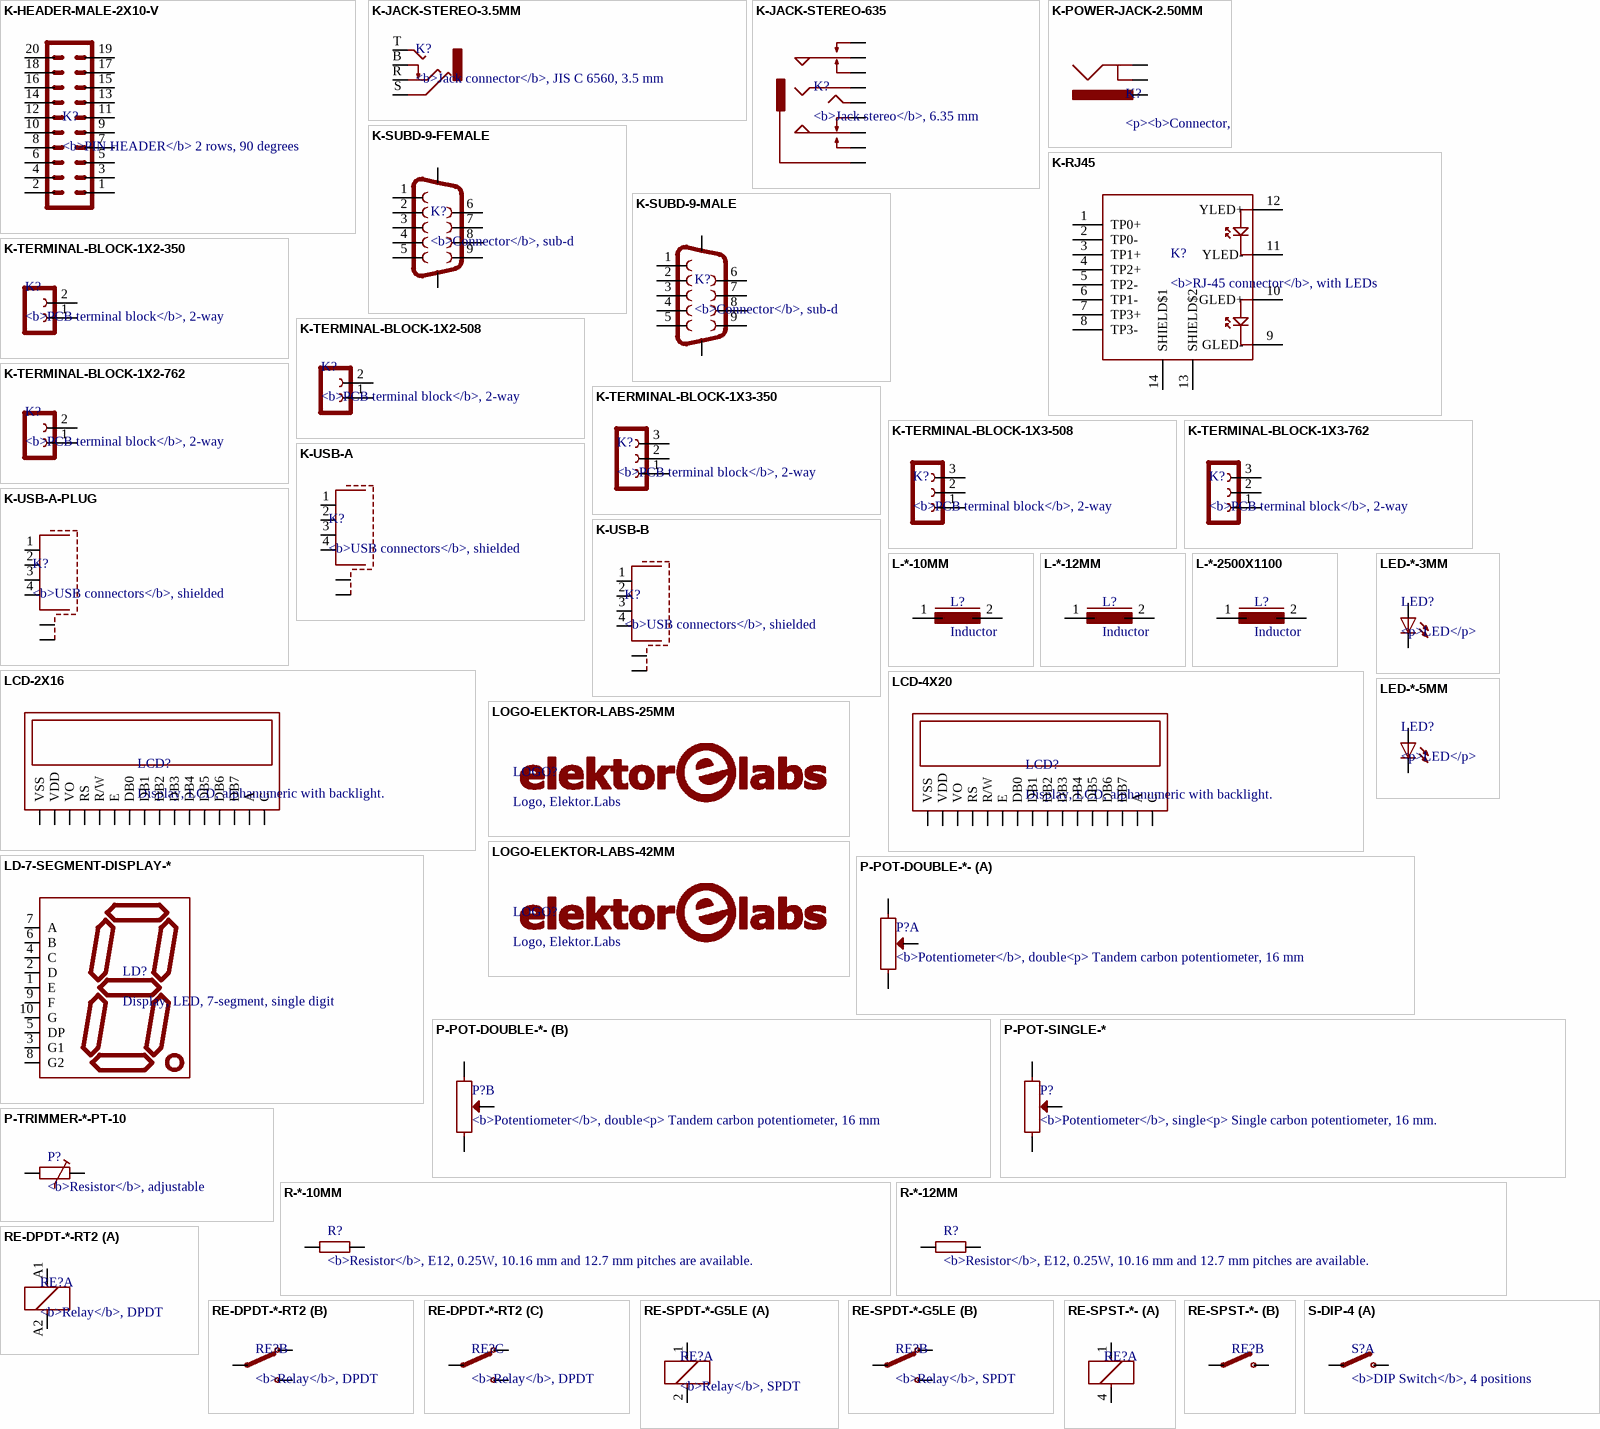
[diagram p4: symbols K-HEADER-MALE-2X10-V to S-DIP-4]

## K-HEADER-MALE-2X10-V
designator K?, comment <b>PIN HEADER</b> 2 rows, 90 degrees
RS: 6812067
footprint ELPP-DIL-M-20-WAY-V
pins: 1, 2, 3, 4, 5, 6, 7, 8, 9, 10, 11, 12, 13, 14, 15, 16, 17, 18, 19, 20

## K-JACK-STEREO-3.5MM
designator K?, comment <b>Jack connector</b>, JIS C 6560, 3.5 mm
RS: 5051479
footprint ELPP-JACK-35
pins: B, R, S, T

## K-JACK-STEREO-635
designator K?, comment <b>Jack stereo</b>, 6.35 mm
RS: 2049114
footprint ELPP-JACK-635
pins: 1, 2, 3, 4, 5, 6, 7, 8, 9

## K-POWER-JACK-2.50MM
designator K?, comment <p><b>Connector, power/barrel jack</b><br> / 2.5 mm center pin diameter<br> / Suitable for flat (slotted) and round pin models / </p>
RS: 5051609
footprint ELPP-DC-195
pins: COMMON, VIN1, VIN2

## K-RJ45
designator K?, comment <b>RJ-45 connector</b>, with LEDs
RS: 7350298
footprint ELPP-RJ45
pins: 1 TP0+, 2 TP0-, 3 TP1+, 4 TP2+, 5 TP2-, 6 TP1-, 7 TP3+, 8 TP3-, 9 GLED-, 10 GLED+, 11 YLED-, 12 YLED+, 13 SHIELD$2, 14 SHIELD$1

## K-SUBD-9-FEMALE
designator K?, comment <b>Connector</b>, sub-d
RS: 495-9760
footprint ELPP-SUBD-9-FEMALE
pins: 1, 2, 3, 4, 5, 6, 7, 8, 9, G1 P$1, G2 P$2

## K-SUBD-9-MALE
designator K?, comment <b>Connector</b>, sub-d
RS: 495-9805
footprint ELPP-SUDB-9-MALE
pins: 1, 2, 3, 4, 5, 6, 7, 8, 9, G1 P$1, G2 P$2

## K-TERMINAL-BLOCK-1X2-350
designator K?, comment <b>PCB terminal block</b>, 2-way
RS: 7100444
footprint ELPP-TB-350-2
pins: 1, 2

## K-TERMINAL-BLOCK-1X2-508
designator K?, comment <b>PCB terminal block</b>, 2-way
RS: 1930586
footprint ELPP-TB-508-2
pins: 1, 2

## K-TERMINAL-BLOCK-1X2-762
designator K?, comment <b>PCB terminal block</b>, 2-way
RS: 1895966
footprint ELPP-TB-762-2
pins: 1, 2

## K-TERMINAL-BLOCK-1X3-350
designator K?, comment <b>PCB terminal block</b>, 2-way
RS: unknown
footprint ELPP-TB-350-3
pins: 1, 2, 3

## K-TERMINAL-BLOCK-1X3-508
designator K?, comment <b>PCB terminal block</b>, 2-way
RS: 1930592
footprint ELPP-TB-508-3
pins: 1, 2, 3

## K-TERMINAL-BLOCK-1X3-762
designator K?, comment <b>PCB terminal block</b>, 2-way
RS: 1895972
footprint ELPP-TB-762-3
pins: 1, 2, 3

## K-USB-A
designator K?, comment <b>USB connectors</b>, shielded
RS: 7710057
footprint ELPP-USB-A
pins: 1, 2, 3, 4, S1, S2

## K-USB-A-PLUG
designator K?, comment <b>USB connectors</b>, shielded
RS: 7378805
footprint ELPP-USB-A-PLUG
pins: 1, 2, 3, 4, S1, S2

## K-USB-B
designator K?, comment <b>USB connectors</b>, shielded
RS: 6741328
footprint ELPP-USB-B
pins: 1, 2, 3, 4, S1, S2

## L-*-10MM
designator L?, comment Inductor
RS: 8604063; RS: 8604060
footprint ELPP-L-0207-1000
pins: 1, 2

## L-*-12MM
designator L?, comment Inductor
RS: 8604063; RS: 8604060
footprint ELPP-L-0207-1200
pins: 1, 2

## L-*-2500X1100
designator L?, comment Inductor
RS: 3088823
footprint ELPP-L-800-2500X1100
pins: 1, 2

## LCD-2X16
designator LCD?, comment Display, LCD, alphanumeric with backlight.
RS: 7200207
footprint ELPP-LCD-2X16
pins: 1 VSS, 2 VDD, 3 VO, 4 RS, 5 R/W, 6 E, 7 DB0, 8 DB1, 9 DB2, 10 DB3, 11 DB4, 12 DB5, 13 DB6, 14 DB7, 15 A, 16 C

## LCD-4X20
designator LCD?, comment Display, LCD, alphanumeric with backlight.
RS: 7200226
footprint ELPP-LCD-4X20
pins: 1 VSS, 2 VDD, 3 VO, 4 RS, 5 R/W, 6 E, 7 DB0, 8 DB1, 9 DB2, 10 DB3, 11 DB4, 12 DB5, 13 DB6, 14 DB7, 15 A, 16 C

## LD-7-SEGMENT-DISPLAY-*
designator LD?, comment Display, LED, 7-segment, single digit
RS: 2358777; RS: 2358783
footprint ELPP-7-SEGMENT-DISPLAY
pins: 1 E, 2 D, 3 G1, 4 C, 5 DP, 6 B, 7 A, 8 G2, 9 F, 10 G

## LED-*-3MM
designator LED?, comment <p>LED</p>
RS: 2471628; RS: 2285944; RS: 2285916; RS: 2285966
footprint ELPP-LED-3MM
pins: A, C

## LED-*-5MM
designator LED?, comment <p>LED</p>
RS: 6997622; RS: 7031152
footprint ELPP-LED-5MM
pins: A, C

## LOGO-ELEKTOR-LABS-25MM
designator LOGO?, comment Logo, Elektor.Labs
footprint ELPP-LOGO-ELEKTOR-LABS-25MM

## LOGO-ELEKTOR-LABS-42MM
designator LOGO?, comment Logo, Elektor.Labs
footprint ELPP-LOGO-ELEKTOR-LABS-42MM

## P-POT-DOUBLE-*-
designator P?, comment <b>Potentiometer</b>, double<p> / Tandem carbon potentiometer, 16 mm
RS: unknown
footprint ELPP-POT-CP16-DOUBLE
part A pins: 1A, 1E, 1S
part B pins: 2A 1A, 2E 1E, 2S 1S

## P-POT-SINGLE-*
designator P?, comment <b>Potentiometer</b>, single<p> / Single carbon potentiometer, 16 mm.
RS: unknown
footprint ELPP-POT-CP16-SINGLE
pins: 1A, 1E, 1S

## P-TRIMMER-*-PT-10
designator P?, comment <b>Resistor</b>, adjustable
RS: 473590; RS: 473473; RS: 473562; RS: 473578; RS: 473580; RS: 473489
footprint ELPP-TRIMMER-CB10-H
pins: 1, 2, 3

## R-*-10MM
designator R?, comment <b>Resistor</b>, E12, 0.25W, 10.16 mm and 12.7 mm pitches are available.
RS: 188374; RS: 135982; RS: 135774; RS: 135910; RS: 135667; RS: 135702; RS: 135998; RS: 135780; RS: 135926; RS: 7077511; RS: 7077849; RS: 135796; RS: 135932; RS: 7077524; RS: 136014; RS: 135803; RS: 135948; RS: 7077521; RS: 135847; RS: 135853; RS: 135869; RS: 135875; RS: 136058; RS: 136064; RS: 136070; RS: 136086; RS: 7077420; RS: 7077432; RS: 7077445; RS: 7077442; RS: 136020; RS: 135819; RS: 135954; RS: 135746; RS: 7077861; RS: 7077625; RS: 7077782; RS: 7077546; RS: 135881; RS: 7077704; RS: 136092; RS: 7077940; RS: 135673; RS: 7077467; RS: 136036; RS: 135825; RS: 135960; RS: 135752; RS: 7077870; RS: 7077634; RS: 7077791; RS: 7077555; RS: 135897; RS: 7077713; RS: 136109; RS: 7077959; RS: 135689; RS: 7077476; RS: 136042; RS: 135831; RS: 135976; RS: 135768; RS: 135904; RS: 136115; RS: 135695; RS: 7077880; RS: 7077644; RS: 7077802; RS: 7077565; RS: 7077723; RS: 7077969; RS: 7077486; RS: 7077892; RS: 7077656; RS: 7077814; RS: 7077577; RS: 7077735; RS: 7077971; RS: 7077498; RS: 7077906; RS: 7077669; RS: 7077827; RS: 7077580; RS: 7077748; RS: 7077984; RS: 7077502
footprint ELPP-R-0207-1000
pins: 1, 2

## R-*-12MM
designator R?, comment <b>Resistor</b>, E12, 0.25W, 10.16 mm and 12.7 mm pitches are available.
RS: 188374; RS: 135982; RS: 135774; RS: 135910; RS: 135667; RS: 135702; RS: 135998; RS: 135780; RS: 135926; RS: 7077511; RS: 7077849; RS: 135796; RS: 135932; RS: 7077524; RS: 136014; RS: 135803; RS: 135948; RS: 7077521; RS: 135847; RS: 135853; RS: 135869; RS: 135875; RS: 136058; RS: 136064; RS: 136070; RS: 136086; RS: 7077420; RS: 7077432; RS: 7077445; RS: 7077442; RS: 136020; RS: 135819; RS: 135954; RS: 135746; RS: 7077861; RS: 7077625; RS: 7077782; RS: 7077546; RS: 135881; RS: 7077704; RS: 136092; RS: 7077940; RS: 135673; RS: 7077467; RS: 136036; RS: 135825; RS: 135960; RS: 135752; RS: 7077870; RS: 7077634; RS: 7077791; RS: 7077555; RS: 135897; RS: 7077713; RS: 136109; RS: 7077959; RS: 135689; RS: 7077476; RS: 136042; RS: 135831; RS: 135976; RS: 135768; RS: 135904; RS: 136115; RS: 135695; RS: 7077880; RS: 7077644; RS: 7077802; RS: 7077565; RS: 7077723; RS: 7077969; RS: 7077486; RS: 7077892; RS: 7077656; RS: 7077814; RS: 7077577; RS: 7077735; RS: 7077971; RS: 7077498; RS: 7077906; RS: 7077669; RS: 7077827; RS: 7077580; RS: 7077748; RS: 7077984; RS: 7077502
footprint ELPP-R-0207-1200
pins: 1, 2

## RE-DPDT-*-RT2
designator RE?, comment <b>Relay</b>, DPDT
RS: 7821264; RS: 1986898
footprint ELPP-RELAY-RT2
part A pins: A1 1, A2 2
part B pins: O1 O, P1 P, S1 S
part C pins: O2 O, P2 P, S2 S

## RE-SPDT-*-G5LE
designator RE?, comment <b>Relay</b>, SPDT
RS: 369466
footprint ELPP-RELAY-G5LE
part A pins: 1, 2
part B pins: O, P, S

## RE-SPST-*-
designator RE?
footprint ELPP-RELAY-G5NB
part A pins: 1, 4 2
part B pins: 2 O, 3 P

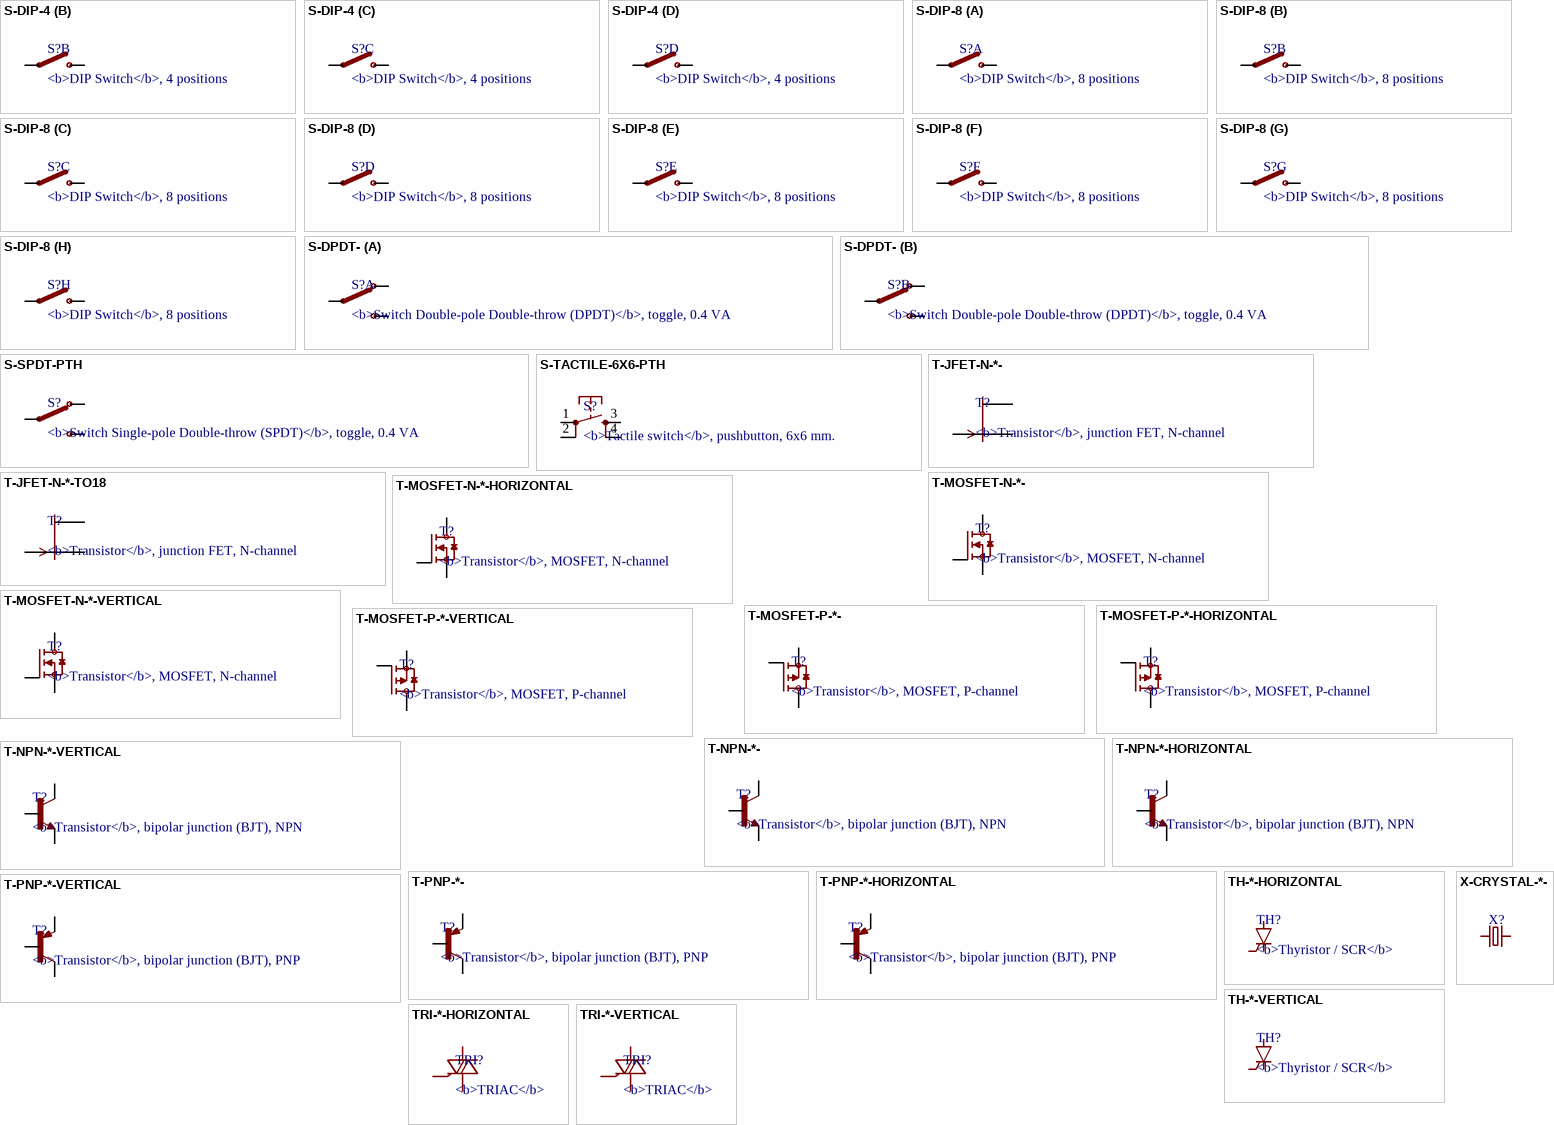
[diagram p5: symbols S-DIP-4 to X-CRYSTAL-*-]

## S-DIP-4
designator S?, comment <b>DIP Switch</b>, 4 positions
RS: 6394727
footprint ELPP-S-DIP4
part A pins: 1 O, 16 P
part B pins: 2 O, 15 P
part C pins: 3 O, 14 P
part D pins: 4 O, 13 P

## S-DIP-8
designator S?, comment <b>DIP Switch</b>, 8 positions
RS: 6393049
footprint ELPP-S-DIP8
part A pins: 1 O, 16 P
part B pins: 2 O, 15 P
part C pins: 3 O, 14 P
part D pins: 4 O, 13 P
part E pins: 5 O, 12 P
part F pins: 6 O, 11 P
part G pins: 7 O, 10 P
part H pins: 8 O, 9 P

## S-DPDT-
designator S?, comment <b>Switch Double-pole Double-throw (DPDT)</b>, toggle, 0.4 VA
RS: 7109983
footprint ELPP-S-TOGGLE-DPDT
part A pins: 1 O, 2 P, 3 S
part B pins: 4 O, 5 P, 6 S

## S-SPDT-PTH
designator S?, comment <b>Switch Single-pole Double-throw (SPDT)</b>, toggle, 0.4 VA
RS: 7109779
footprint ELPP-S-TOGGLE-SPDT
pins: 1 O, 2 P, 3 S

## S-TACTILE-6X6-PTH
designator S?, comment <b>Tactile switch</b>, pushbutton, 6x6 mm.
RS: 4791435
footprint ELPP-S-TACT-6X6
pins: 1, 2, 3, 4

## T-JFET-N-*-
designator T?, comment <b>Transistor</b>, junction FET, N-channel
footprint ELPP-TO-92
pins: 1 D, 2 S, 3 G

## T-JFET-N-*-TO18
designator T?, comment <b>Transistor</b>, junction FET, N-channel
RS: 7082832
footprint ELPP-TO-18
pins: 1 S, 2 D, 3 G

## T-MOSFET-N-*-
designator T?, comment <b>Transistor</b>, MOSFET, N-channel
RS: 6714736
footprint ELPP-TO-92
pins: 1 D, 2 G, 3 S

## T-MOSFET-N-*-HORIZONTAL
designator T?, comment <b>Transistor</b>, MOSFET, N-channel
RS: 5409941
footprint ELPP-TO-220-H
pins: 1 G, 2 D, 3 S

## T-MOSFET-N-*-VERTICAL
designator T?, comment <b>Transistor</b>, MOSFET, N-channel
RS: 5409941
footprint ELPP-TO-220-V
pins: 1 G, 2 D, 3 S

## T-MOSFET-P-*-
designator T?, comment <b>Transistor</b>, MOSFET, P-channel
RS: 6697596P
footprint ELPP-TO-92
pins: 1 S, 2 G, 3 D

## T-MOSFET-P-*-HORIZONTAL
designator T?, comment <b>Transistor</b>, MOSFET, P-channel
RS: 6715064
footprint ELPP-TO-220-H
pins: 1 G, 2 D, 3 S

## T-MOSFET-P-*-VERTICAL
designator T?, comment <b>Transistor</b>, MOSFET, P-channel
RS: 6715064
footprint ELPP-TO-220-V
pins: 1 G, 2 D, 3 S

## T-NPN-*-
designator T?, comment <b>Transistor</b>, bipolar junction (BJT), NPN
RS: 6254966; RS: 5452248
footprint ELPP-TO-92
pins: 1 C, 2 B, 3 E

## T-NPN-*-HORIZONTAL
designator T?, comment <b>Transistor</b>, bipolar junction (BJT), NPN
RS: 4369779
footprint ELPP-TO-220-H
pins: 1 B, 2 C, 3 E

## T-NPN-*-VERTICAL
designator T?, comment <b>Transistor</b>, bipolar junction (BJT), NPN
RS: 4369779
footprint ELPP-TO-220-V
pins: 1 B, 2 C, 3 E

## T-PNP-*-
designator T?, comment <b>Transistor</b>, bipolar junction (BJT), PNP
RS: 8009566; RS: 4380619
footprint ELPP-TO-92
pins: 1 C, 2 B, 3 E

## T-PNP-*-HORIZONTAL
designator T?, comment <b>Transistor</b>, bipolar junction (BJT), PNP
RS: 4859654
footprint ELPP-TO-220-H
pins: 1 B, 2 C, 3 E

## T-PNP-*-VERTICAL
designator T?, comment <b>Transistor</b>, bipolar junction (BJT), PNP
RS: 4859654
footprint ELPP-TO-220-V
pins: 1 B, 2 C, 3 E

## TH-*-HORIZONTAL
designator TH?, comment <b>Thyristor / SCR</b>
RS: 3552841
footprint ELPP-TO-220-H
pins: 1 C, 2 A, 3 G

## TH-*-VERTICAL
designator TH?, comment <b>Thyristor / SCR</b>
RS: 3552841
footprint ELPP-TO-220-V
pins: 1 C, 2 A, 3 G

## TRI-*-HORIZONTAL
designator TRI?, comment <b>TRIAC</b>
RS: 508670
footprint ELPP-TO-220-H
pins: 1 T1, 2 T2, 3 G

## TRI-*-VERTICAL
designator TRI?, comment <b>TRIAC</b>
RS: 508670
footprint ELPP-TO-220-V
pins: 1 T1, 2 T2, 3 G

## X-CRYSTAL-*-
designator X?
RS: 6938803; RS: 6938819; RS: 6938825; RS: 6936955
footprint ELPP-HC49
pins: 1, 2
